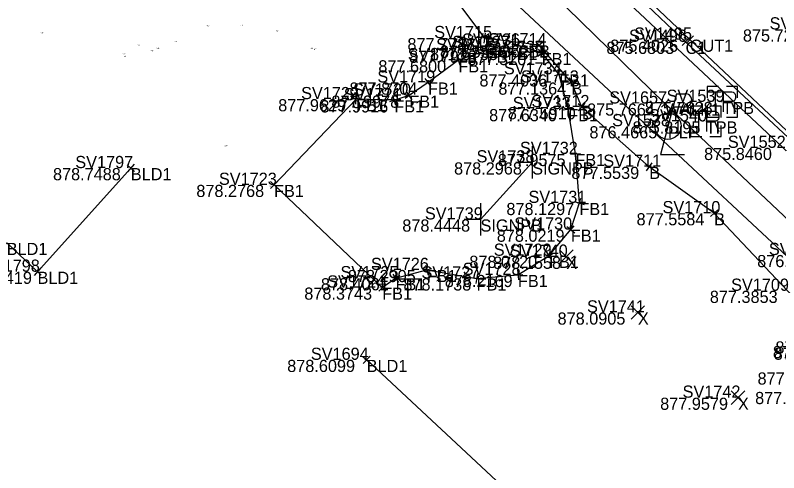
# Model space of a CAD drawing. Extents: x 1469677 to 1493262, y 375219 to 389293.
# Drawn here: x 1480149.3 to 1480224.6, y 379313.5 to 379358.7 of the extents above; entities that cross this region are included whole.
import ezdxf

# ---------------------------------------------------------------- set-up
doc = ezdxf.new("R2010")
doc.units = 0
for name, color, linetype in [('Border', 7, 'Continuous'), ('Default', 7, 'Continuous'), ('DR_X_Drive_Pipe', 7, 'Continuous'), ('DV_X_Lot_Line', 7, 'Continuous'), ('DV_X_Text', 7, 'Continuous'), ('GK_Visualization', 7, 'Continuous'), ('PNTELEV', 7, 'Continuous'), ('PNTS', 7, 'Continuous'), ('RD_P_Text', 7, 'Continuous'), ('RW_P_Esmt_SW', 7, 'Continuous'), ('RW_P_Esmt_U', 7, 'Continuous'), ('rw_x_right_of_way', 7, 'Continuous'), ('SV_P_Mon_Cells_Set', 7, 'Continuous'), ('SV_X_Mon_Cells_Found', 7, 'Continuous'), ('text', 7, 'Continuous'), ('Text Property', 7, 'Continuous')]:
    doc.layers.add(name, color=color, linetype=linetype)

msp = doc.modelspace()

# ---------------------------------------------------------------- linework, layer by layer
at = {"layer": 'Border'}
for points in [[(1480160.694, 379343.603), (1480151.489, 379333.371), (1480148.445, 379336.223), (1480129.012, 379315.639)], [(1480183.972, 379324.669), (1480206.583, 379303.558)]]:
    msp.add_lwpolyline(points, dxfattribs=at)
at = {"layer": 'Default'}
msp.add_lwpolyline([(1480200.308, 379344.167), (1480195.208, 379338.532)], dxfattribs=at)
at = {"layer": 'DR_X_Drive_Pipe'}
msp.add_lwpolyline([(1480327.263, 379249.797), (1480312.798, 379263.799), (1480291.915, 379283.182), (1480274.385, 379298.987), (1480265.401, 379307.725), (1480264.495, 379308.458), (1480240.472, 379331.084), (1480234.677, 379335.863), (1480225.088, 379345.601), (1480208.322, 379361.342), (1480207.346, 379362.25), (1480199.528, 379369.768), (1480193.21, 379375.651), (1480182.823, 379385.139), (1480177.927, 379389.525), (1480169.423, 379398.321), (1480161.035, 379406.189), (1480144.924, 379421.019), (1480134.739, 379430.559), (1480121.485, 379441.998)], dxfattribs=at)
at = {"layer": 'DV_X_Lot_Line'}
msp.add_lwpolyline([(1480327.959, 379242.083), (1480313.163, 379256.356), (1480297.576, 379270.674), (1480283.951, 379284.205), (1480267.344, 379299.69), (1480258.509, 379307.782), (1480244.036, 379321.372), (1480229.243, 379335.021), (1480213.414, 379349.982), (1480196.806, 379366.202), (1480192.296, 379370.271), (1480186.385, 379375.802), (1480181.8, 379379.27), (1480179.258, 379381.212), (1480177.445, 379382.131), (1480174.921, 379382.868), (1480171.98, 379383.537), (1480169.491, 379383.403), (1480167.014, 379382.902), (1480162.891, 379380.83), (1480161.298, 379379.691), (1480158.915, 379377.808)], dxfattribs=at)
at = {"layer": 'PNTELEV'}
for p, q in [((1480195.562, 379355.945), (1480195.694, 379356.936)), ((1480196.124, 379356.375), (1480195.132, 379356.506)), ((1480195.628, 379356.44), (1480195.628, 379356.44)), ((1480198.8, 379355.224), (1480199.104, 379356.177)), ((1480201.321, 379355.352), (1480200.665, 379356.107)), ((1480215.812, 379355.733), (1480215.081, 379356.416)), ((1480215.105, 379355.709), (1480215.788, 379356.44)), ((1480215.447, 379356.074), (1480215.447, 379356.074)), ((1480216.239, 379355.946), (1480215.511, 379356.631)), ((1480215.532, 379355.924), (1480216.218, 379356.653)), ((1480215.875, 379356.288), (1480215.875, 379356.288)), ((1480196.287, 379355.36), (1480195.339, 379355.039)), ((1480195.974, 379354.726), (1480195.652, 379355.673)), ((1480198.375, 379355.576), (1480197.397, 379355.366)), ((1480197.991, 379354.982), (1480197.781, 379355.96)), ((1480197.886, 379355.471), (1480197.886, 379355.471)), ((1480199.428, 379355.549), (1480198.476, 379355.852)), ((1480198.952, 379355.701), (1480198.952, 379355.701)), ((1480200.615, 379355.401), (1480201.371, 379356.057)), ((1480201.562, 379354.585), (1480200.926, 379355.357)), ((1480200.993, 379355.729), (1480200.993, 379355.729)), ((1480193.184, 379353.78), (1480192.862, 379354.727)), ((1480195.813, 379355.199), (1480195.813, 379355.199)), ((1480200.858, 379354.653), (1480201.63, 379355.289)), ((1480201.244, 379354.971), (1480201.244, 379354.971)), ((1480193.497, 379354.414), (1480192.549, 379354.093)), ((1480193.023, 379354.253), (1480193.023, 379354.253)), ((1480203.108, 379352.377), (1480202.858, 379353.345)), ((1480190.43, 379352.353), (1480189.624, 379351.762)), ((1480190.323, 379351.654), (1480189.731, 379352.461)), ((1480202.499, 379352.735), (1480203.467, 379352.986)), ((1480202.983, 379352.861), (1480202.983, 379352.861)), ((1480204.383, 379351.591), (1480203.991, 379352.511)), ((1480190.027, 379352.057), (1480190.027, 379352.057)), ((1480203.727, 379351.855), (1480204.647, 379352.246)), ((1480204.187, 379352.051), (1480204.187, 379352.051)), ((1480182.918, 379349.911), (1480182.948, 379350.911)), ((1480188.589, 379351.054), (1480187.769, 379350.481)), ((1480188.465, 379350.357), (1480187.893, 379351.177)), ((1480183.433, 379350.396), (1480182.433, 379350.426)), ((1480182.933, 379350.411), (1480182.933, 379350.411)), ((1480187.18, 379350.448), (1480186.228, 379350.144)), ((1480186.856, 379349.82), (1480186.552, 379350.772)), ((1480186.704, 379350.296), (1480186.704, 379350.296)), ((1480188.179, 379350.767), (1480188.179, 379350.767)), ((1480213.777, 379349.638), (1480213.051, 379350.325)), ((1480213.071, 379349.618), (1480213.757, 379350.345)), ((1480203.378, 379349.353), (1480204.366, 379349.509)), ((1480203.95, 379348.937), (1480203.794, 379349.925)), ((1480203.872, 379349.431), (1480203.872, 379349.431)), ((1480205.594, 379349.292), (1480204.846, 379349.956)), ((1480204.888, 379349.25), (1480205.552, 379349.998)), ((1480205.22, 379349.624), (1480205.22, 379349.624)), ((1480213.414, 379349.982), (1480213.414, 379349.982)), ((1480204.073, 379344.962), (1480205.069, 379345.044)), ((1480204.612, 379344.505), (1480204.53, 379345.501)), ((1480204.571, 379345.003), (1480204.571, 379345.003)), ((1480212.272, 379343.441), (1480211.458, 379344.023)), ((1480211.574, 379343.326), (1480212.156, 379344.139)), ((1480161.066, 379343.269), (1480160.322, 379343.937)), ((1480161.028, 379343.975), (1480160.36, 379343.231)), ((1480160.694, 379343.603), (1480160.694, 379343.603)), ((1480211.865, 379343.732), (1480211.865, 379343.732)), ((1480175.192, 379341.604), (1480174.47, 379342.295)), ((1480175.177, 379342.311), (1480174.485, 379341.588)), ((1480174.831, 379341.95), (1480174.831, 379341.95)), ((1480204.494, 379340.318), (1480205.446, 379340.013)), ((1480204.817, 379339.689), (1480205.123, 379340.642)), ((1480204.97, 379340.165), (1480204.97, 379340.165)), ((1480217.901, 379338.808), (1480218.627, 379339.495)), ((1480218.608, 379338.789), (1480217.92, 379339.515)), ((1480218.264, 379339.152), (1480218.264, 379339.152)), ((1480203.741, 379337.851), (1480204.509, 379337.21)), ((1480203.804, 379337.147), (1480204.446, 379337.914)), ((1480204.125, 379337.531), (1480204.125, 379337.531)), ((1480201.54, 379334.685), (1480202.392, 379335.21)), ((1480201.703, 379335.373), (1480202.229, 379334.522)), ((1480201.966, 379334.947), (1480201.966, 379334.947)), ((1480151.861, 379333.037), (1480151.117, 379333.706)), ((1480151.823, 379333.743), (1480151.155, 379333)), ((1480189.43, 379333.418), (1480190.396, 379333.673)), ((1480189.785, 379334.029), (1480190.041, 379333.062)), ((1480189.913, 379333.545), (1480189.913, 379333.545)), ((1480198.86, 379333.555), (1480198.944, 379332.559)), ((1480151.489, 379333.371), (1480151.489, 379333.371)), ((1480186.42, 379332.446), (1480187.24, 379333.018)), ((1480186.544, 379333.142), (1480187.116, 379332.322)), ((1480186.83, 379332.732), (1480186.83, 379332.732)), ((1480194.327, 379332.797), (1480195.313, 379332.63)), ((1480194.904, 379333.207), (1480194.736, 379332.221)), ((1480194.82, 379332.714), (1480194.82, 379332.714)), ((1480198.404, 379333.015), (1480199.4, 379333.099)), ((1480198.902, 379333.057), (1480198.902, 379333.057)), ((1480185.144, 379332.154), (1480185.87, 379331.465)), ((1480185.851, 379332.172), (1480185.163, 379331.447)), ((1480185.507, 379331.81), (1480185.507, 379331.81)), ((1480183.607, 379325.01), (1480184.337, 379324.328)), ((1480184.313, 379325.035), (1480183.631, 379324.304)), ((1480183.972, 379324.669), (1480183.972, 379324.669))]:
    msp.add_line(p, q, dxfattribs=at)
at = {"layer": 'PNTS'}
for p, q in [((1480214.563, 379350.941), (1480215.413, 379350.941)), ((1480214.221, 379349.666), (1480215.413, 379349.666))]:
    msp.add_line(p, q, dxfattribs=at)
msp.add_lwpolyline([(1480214.563, 379350.941), (1480212.956, 379344.941), (1480215.356, 379344.941)], dxfattribs=at)
msp.add_circle((1480213.706, 379347.741), 1.3, dxfattribs=at)
msp.add_arc((1480215.425, 379350.303), 0.638, 268.8767, 91.1233, dxfattribs=at)
at = {"layer": 'RD_P_Text'}
for points in [[(1480264.304, 379310.926), (1480249.8, 379324.506), (1480248.109, 379326.126), (1480239.302, 379334.68), (1480237.065, 379336.683), (1480233.83, 379339.39), (1480215.875, 379356.288), (1480200.731, 379370.664), (1480190.903, 379379.712), (1480187.53, 379382.642), (1480185.615, 379384.173), (1480181.928, 379385.583), (1480179.411, 379386.173), (1480174.793, 379387.235), (1480172.715, 379387.432), (1480170.332, 379387.359), (1480168.876, 379387.382), (1480166.808, 379386.944), (1480164.881, 379386.368), (1480162.883, 379385.531), (1480159.898, 379383.853), (1480158.052, 379382.754), (1480156.183, 379381.403), (1480155.05, 379380.342)], [(1480233.297, 379339.4), (1480215.447, 379356.074), (1480200.436, 379370.31), (1480191.889, 379378.223), (1480190.185, 379379.842), (1480188.303, 379381.604), (1480185.259, 379383.605), (1480181.861, 379385.001), (1480179.101, 379385.902), (1480178.705, 379386.045), (1480178.118, 379386.223), (1480177.29, 379386.43), (1480176.688, 379386.511), (1480174.95, 379386.851), (1480173.419, 379387.005), (1480171.202, 379387.128), (1480169.933, 379386.966), (1480168.123, 379386.781), (1480166.87, 379386.446), (1480165.488, 379386.008), (1480163.201, 379385.04), (1480160.165, 379383.332), (1480157.23, 379381.331), (1480156.058, 379380.439)]]:
    msp.add_lwpolyline(points, dxfattribs=at)
at = {"layer": 'RW_P_Esmt_U'}
for p, q in [((1480203.011, 379334.187), (1480204.345, 379335.522)), ((1480203.011, 379335.522), (1480204.345, 379334.187)), ((1480210.073, 379328.679), (1480211.407, 379330.014)), ((1480210.073, 379330.014), (1480211.407, 379328.679)), ((1480219.946, 379320.266), (1480221.28, 379321.601)), ((1480219.946, 379321.601), (1480221.28, 379320.266))]:
    msp.add_line(p, q, dxfattribs=at)
at = {"layer": 'rw_x_right_of_way'}
for p, q in [((1480200.308, 379345.767), (1480200.308, 379342.567)), ((1480200.308, 379344.167), (1480198.708, 379344.167)), ((1480195.208, 379340.132), (1480195.208, 379336.932)), ((1480195.208, 379338.532), (1480193.608, 379338.532))]:
    msp.add_line(p, q, dxfattribs=at)
at = {"layer": 'SV_P_Mon_Cells_Set'}
for p, q in [((1480219.083, 379350.144), (1480219.083, 379350.144)), ((1480217.444, 379348.213), (1480217.444, 379348.213))]:
    msp.add_line(p, q, dxfattribs=at)
for points in [[(1480218.683, 379351.644), (1480217.583, 379351.644), (1480217.583, 379350.544)], [(1480220.582, 379350.544), (1480220.582, 379351.644), (1480219.483, 379351.644)], [(1480217.726, 379351.144), (1480218.97, 379351.144)], [(1480218.356, 379351.144), (1480218.356, 379349.144)], [(1480219.195, 379349.144), (1480219.195, 379351.144), (1480219.95, 379351.144), (1480220.029, 379351.128), (1480220.139, 379351.097), (1480220.186, 379351.065), (1480220.234, 379351.034), (1480220.297, 379350.955), (1480220.344, 379350.876), (1480220.375, 379350.751), (1480220.375, 379350.562), (1480220.36, 379350.499), (1480220.328, 379350.404), (1480220.265, 379350.294), (1480220.202, 379350.247), (1480220.155, 379350.215), (1480220.123, 379350.199), (1480220.076, 379350.184), (1480219.934, 379350.168), (1480219.195, 379350.168)], [(1480219.934, 379350.168), (1480220.375, 379349.144)], [(1480217.044, 379349.713), (1480215.944, 379349.713), (1480215.944, 379348.613)], [(1480217.583, 379349.744), (1480217.583, 379348.644), (1480218.683, 379348.644)], [(1480218.944, 379348.613), (1480218.944, 379349.713), (1480217.844, 379349.713)], [(1480219.483, 379348.644), (1480220.582, 379348.644), (1480220.582, 379349.744)], [(1480216.088, 379349.213), (1480217.332, 379349.213)], [(1480216.718, 379349.213), (1480216.718, 379347.213)], [(1480217.556, 379347.213), (1480217.556, 379349.213), (1480218.312, 379349.213), (1480218.391, 379349.197), (1480218.501, 379349.166), (1480218.548, 379349.134), (1480218.595, 379349.103), (1480218.658, 379349.024), (1480218.706, 379348.945), (1480218.737, 379348.819), (1480218.737, 379348.63), (1480218.721, 379348.567), (1480218.69, 379348.473), (1480218.627, 379348.363), (1480218.564, 379348.316), (1480218.517, 379348.284), (1480218.485, 379348.268), (1480218.438, 379348.253), (1480218.296, 379348.237), (1480217.556, 379348.237)], [(1480215.944, 379347.813), (1480215.944, 379346.713), (1480217.044, 379346.713)], [(1480217.844, 379346.713), (1480218.944, 379346.713), (1480218.944, 379347.813)], [(1480218.296, 379348.237), (1480218.737, 379347.213)]]:
    msp.add_lwpolyline(points, dxfattribs=at)
at = {"layer": 'SV_X_Mon_Cells_Found'}
msp.add_lwpolyline([(1477164.629, 382297.849), (1479615.888, 379904.59), (1480413.414, 379159.216)], dxfattribs=at)
at = {"layer": 'text'}
msp.add_lwpolyline([(1480230.882, 379325.878), (1480225.522, 379331.489), (1480218.264, 379339.152), (1480211.865, 379343.732), (1480205.22, 379349.624), (1480204.187, 379352.051), (1480200.993, 379355.729), (1480195.628, 379356.44), (1480192.91, 379360.091)], dxfattribs=at)
at = {"layer": 'Text Property'}
msp.add_lwpolyline([(1480195.813, 379355.199), (1480193.023, 379354.253), (1480190.027, 379352.057), (1480188.179, 379350.767), (1480186.704, 379350.296), (1480182.933, 379350.411), (1480174.831, 379341.95), (1480185.507, 379331.81), (1480186.83, 379332.732), (1480189.913, 379333.545), (1480194.82, 379332.714), (1480198.902, 379333.057), (1480201.966, 379334.947), (1480204.125, 379337.531), (1480204.97, 379340.165), (1480204.571, 379345.003), (1480203.872, 379349.431), (1480202.983, 379352.861), (1480201.244, 379354.971), (1480198.952, 379355.701), (1480197.886, 379355.471)], close=True, dxfattribs=at)

# ---------------------------------------------------------------- texts
at = {"layer": 'DV_X_Text'}
for s, height, p in [('878.12', 0.06, (1480168.206, 379357.588)), ('878.05', 0.06, (1480171.53, 379357.642)), ('878.17', 0.06, (1480151.826, 379356.898)), ('878.09', 0.06, (1480175.009, 379357.083)), ('875.7225', 1.2, (1480221.105, 379356.097)), ('878.18', 0.06, (1480165.022, 379356.066)), ('877.7788', 1.2, (1480187.994, 379355.24)), ('877.78', 0.06, (1480195.349, 379356.38)), ('875.6803', 1.2, (1480207.633, 379354.874)), ('875.4026', 1.2, (1480208.014, 379355.088)), ('875.68', 0.06, (1480215.165, 379356.014)), ('875.40', 0.06, (1480215.589, 379356.228)), ('878.36', 0.06, (1480161.358, 379355.681)), ('878.34', 0.06, (1480163.27, 379355.378)), ('877.98', 0.06, (1480178.413, 379355.373)), ('878.15', 0.06, (1480178.754, 379355.266)), ('877.5735', 1.2, (1480190.224, 379354.271)), ('877.5546', 1.2, (1480191.205, 379354.501)), ('877.3362', 1.2, (1480193.283, 379354.529)), ('877.57', 0.06, (1480197.607, 379355.411)), ('877.55', 0.06, (1480198.673, 379355.641)), ('877.34', 0.06, (1480200.713, 379355.669)), ('878.29', 0.06, (1480159.878, 379354.801)), ('878.56', 0.06, (1480160.028, 379354.579)), ('878.36', 0.06, (1480162.674, 379355.141)), ('877.7928', 1.2, (1480188.16, 379353.999)), ('877.3201', 1.2, (1480193.919, 379353.771)), ('877.79', 0.06, (1480195.534, 379355.139)), ('877.32', 0.06, (1480200.964, 379354.911)), ('877.6800', 1.2, (1480185.124, 379353.053)), ('877.68', 0.06, (1480192.742, 379354.193)), ('877.4036', 1.2, (1480195.103, 379351.661)), ('877.40', 0.06, (1480202.698, 379352.801)), ('877.8704', 1.2, (1480182.279, 379350.857)), ('877.87', 0.06, (1480189.748, 379351.997)), ('877.1364', 1.2, (1480196.969, 379350.851)), ('877.14', 0.06, (1480203.932, 379351.991)), ('877.9629', 1.2, (1480175.242, 379349.211)), ('877.9916', 1.2, (1480179.401, 379349.096)), ('877.9978', 1.2, (1480180.488, 379349.567)), ('878.18', 0.06, (1480182.385, 379350.552)), ('877.96', 0.06, (1480182.649, 379350.351)), ('877.99', 0.06, (1480186.423, 379350.236)), ('878.00', 0.06, (1480187.888, 379350.707)), ('875.7828', 1.2, (1480211.429, 379348.944)), ('875.78', 0.06, (1480218.803, 379350.084)), ('877.6340', 1.2, (1480196.058, 379348.231)), ('877.5910', 1.2, (1480197.908, 379348.424)), ('877.63', 0.06, (1480203.592, 379349.371)), ('877.59', 0.06, (1480204.94, 379349.564)), ('875.7664', 1.2, (1480205.723, 379348.782)), ('875.77', 0.06, (1480213.135, 379349.922)), ('875.8195', 1.2, (1480210.217, 379347.013)), ('875.82', 0.06, (1480217.164, 379348.153)), ('876.4665', 1.2, (1480205.958, 379346.541)), ('876.47', 0.06, (1480213.424, 379347.681)), ('878.60', 0.06, (1480169.939, 379345.76)), ('875.8460', 1.2, (1480217.274, 379344.401)), ('877.9575', 1.2, (1480196.909, 379343.803)), ('877.96', 0.06, (1480204.287, 379344.943)), ('878.2968', 1.2, (1480192.598, 379342.967)), ('878.30', 0.06, (1480200.022, 379344.107)), ('878.7488', 1.2, (1480153.013, 379342.403)), ('878.75', 0.06, (1480160.415, 379343.543)), ('877.5539', 1.2, (1480204.174, 379342.532)), ('877.55', 0.06, (1480211.586, 379343.672)), ('878.2768', 1.2, (1480167.159, 379340.75)), ('878.57', 0.06, (1480174.361, 379341.757)), ('878.28', 0.06, (1480174.551, 379341.89)), ('878.1297', 1.2, (1480197.762, 379338.965)), ('878.13', 0.06, (1480204.714, 379340.105)), ('877.5584', 1.2, (1480210.611, 379337.952)), ('877.56', 0.06, (1480217.981, 379339.092)), ('878.4448', 1.2, (1480187.489, 379337.332)), ('878.44', 0.06, (1480194.928, 379338.472)), ('878.0219', 1.2, (1480196.813, 379336.331)), ('878.02', 0.06, (1480203.84, 379337.471)), ('876.1212', 1.2, (1480222.517, 379333.821)), ('878.0720', 1.2, (1480194.105, 379333.747)), ('878.1558', 1.2, (1480196.46, 379333.655)), ('878.07', 0.06, (1480201.68, 379334.887)), ('878.16', 0.06, (1480203.418, 379334.795)), ('878.2905', 1.2, (1480182.118, 379332.345)), ('878.29', 0.06, (1480189.633, 379333.485)), ('878.6419', 1.2, (1480144.243, 379332.171)), ('878.64', 0.06, (1480151.208, 379333.311)), ('878.4061', 1.2, (1480179.458, 379331.532)), ('878.41', 0.06, (1480186.572, 379332.672)), ('878.1738', 1.2, (1480187.602, 379331.514)), ('878.2169', 1.2, (1480191.684, 379331.857)), ('878.17', 0.06, (1480194.564, 379332.654)), ('878.22', 0.06, (1480198.623, 379332.997)), ('878.3743', 1.2, (1480177.816, 379330.61)), ('878.37', 0.06, (1480185.226, 379331.75)), ('877.3853', 1.2, (1480217.841, 379330.289)), ('878.0905', 1.2, (1480202.813, 379328.146)), ('878.09', 0.06, (1480210.454, 379329.286)), ('877.4189', 1.2, (1480224.058, 379324.834)), ('877.4361', 1.2, (1480224.313, 379325.293)), ('877.6117', 1.2, (1480224.147, 379324.678)), ('878.6099', 1.2, (1480176.13, 379323.469)), ('878.61', 0.06, (1480183.713, 379324.609)), ('877.6009', 1.2, (1480222.552, 379322.226)), ('877.5908', 1.2, (1480222.312, 379320.303)), ('877.9579', 1.2, (1480212.941, 379319.733)), ('877.96', 0.06, (1480220.329, 379320.873))]:
    msp.add_text(s, height=height, dxfattribs=at).set_placement(p)
at = {"layer": 'GK_Visualization'}
for s, p in [('B', (1480195.628, 379355.24)), ('C1', (1480215.447, 379354.874)), ('GUT1', (1480215.875, 379355.088)), ('FB1', (1480197.886, 379354.271)), ('FB1', (1480198.952, 379354.501)), ('B', (1480200.993, 379354.529)), ('FB1', (1480195.813, 379353.999)), ('FB1', (1480201.244, 379353.771)), ('FB1', (1480193.023, 379353.053)), ('FB1', (1480202.983, 379351.661)), ('FB1', (1480190.027, 379350.857)), ('B', (1480204.187, 379350.851)), ('FB1', (1480182.933, 379349.211)), ('FB1', (1480186.704, 379349.096)), ('FB1', (1480188.179, 379349.567)), ('TPB', (1480219.083, 379348.944)), ('FB1', (1480203.872, 379348.231)), ('B', (1480205.22, 379348.424)), ('WALK1', (1480213.414, 379348.782)), ('TPB', (1480217.444, 379347.013)), ('PLP', (1480213.706, 379346.541)), ('FB1', (1480204.571, 379343.803)), ('SIGNPB', (1480200.308, 379342.967)), ('BLD1', (1480160.694, 379342.403)), ('B', (1480211.865, 379342.532)), ('FB1', (1480174.831, 379340.75)), ('FB1', (1480204.97, 379338.965)), ('B', (1480218.264, 379337.952)), ('SIGNPB', (1480195.208, 379337.332)), ('FB1', (1480204.125, 379336.331)), ('BLD1', (1480148.445, 379335.023)), ('FB1', (1480201.966, 379333.747)), ('X', (1480203.678, 379333.655)), ('FB1', (1480189.913, 379332.345)), ('BLD1', (1480151.489, 379332.171)), ('FB1', (1480186.83, 379331.532)), ('FB1', (1480194.82, 379331.514)), ('FB1', (1480198.902, 379331.857)), ('FB1', (1480185.507, 379330.61)), ('X', (1480210.74, 379328.146)), ('BLD1', (1480183.972, 379323.469)), ('X', (1480220.613, 379319.733))]:
    msp.add_text(s, height=1.2, dxfattribs=at).set_placement(p)
at = {"layer": 'RW_P_Esmt_SW'}
for s, height, p in [('SV1215', 1.2, (1480223.742, 379357.297)), ('SA2050', 0.06, (1480168.154, 379357.648)), ('SA2049', 0.06, (1480171.513, 379357.702)), ('SV1715', 1.2, (1480190.641, 379356.44)), ('SA2083', 0.06, (1480151.78, 379356.958)), ('SA2048', 0.06, (1480174.992, 379357.143)), ('SV1736', 1.2, (1480193.397, 379355.701)), ('SV1714', 1.2, (1480196.015, 379355.729)), ('SV1496', 1.2, (1480209.864, 379356.074)), ('SV1495', 1.2, (1480210.367, 379356.288)), ('SA2051', 0.06, (1480164.999, 379356.126)), ('SV1717', 1.2, (1480190.826, 379355.199)), ('SV1737', 1.2, (1480192.407, 379355.471)), ('SV1715', 0.06, (1480195.379, 379356.44)), ('SV1735', 1.2, (1480195.765, 379354.971)), ('SV1496', 0.06, (1480215.168, 379356.074)), ('SV1495', 0.06, (1480215.6, 379356.288)), ('SA2054', 0.06, (1480161.341, 379355.741)), ('SA2052', 0.06, (1480163.248, 379355.438)), ('SA2047', 0.06, (1480178.391, 379355.433)), ('SA2017', 0.06, (1480178.732, 379355.326)), ('SV1718', 1.2, (1480188.026, 379354.253)), ('SV1737', 0.06, (1480197.612, 379355.471)), ('SV1736', 0.06, (1480198.674, 379355.701)), ('SV1714', 0.06, (1480200.744, 379355.729)), ('SA2055', 0.06, (1480159.855, 379354.861)), ('SA2015', 0.06, (1480160.034, 379354.639)), ('SA2053', 0.06, (1480162.657, 379355.201)), ('SV1717', 0.06, (1480195.564, 379355.199)), ('SV1735', 0.06, (1480200.97, 379354.971)), ('SV1718', 0.06, (1480192.773, 379354.253)), ('SV1734', 1.2, (1480197.513, 379352.861)), ('SV1719', 1.2, (1480185.03, 379352.057)), ('SV1713', 1.2, (1480199.2, 379352.051)), ('SV1734', 0.06, (1480202.71, 379352.861)), ('SV1722', 1.2, (1480177.501, 379350.411)), ('SV1720', 1.2, (1480182.634, 379350.767)), ('SV1719', 0.06, (1480189.777, 379352.057)), ('SV1713', 0.06, (1480203.938, 379352.051)), ('SV1721', 1.2, (1480181.714, 379350.296)), ('SV1720', 0.06, (1480187.902, 379350.767)), ('SV1712', 1.2, (1480200.242, 379349.624)), ('SV1657', 1.2, (1480207.916, 379349.982)), ('SV1539', 1.2, (1480213.575, 379350.144)), ('SA2045', 0.06, (1480182.339, 379350.612)), ('SV1722', 0.06, (1480182.661, 379350.411)), ('SV1721', 0.06, (1480186.454, 379350.296)), ('SV1733', 1.2, (1480198.393, 379349.431)), ('SV1657', 0.06, (1480213.139, 379349.982)), ('SV1539', 0.06, (1480218.808, 379350.144)), ('SV1733', 0.06, (1480203.598, 379349.431)), ('SV1712', 0.06, (1480204.971, 379349.624)), ('SV1540', 1.2, (1480211.851, 379348.213)), ('SV1538', 1.2, (1480208.198, 379347.741)), ('SV1538', 0.06, (1480213.431, 379347.741)), ('SV1540', 0.06, (1480217.164, 379348.213)), ('SV1552', 1.2, (1480219.618, 379345.601)), ('SA2016', 0.06, (1480169.943, 379345.82)), ('SV1732', 1.2, (1480199.101, 379345.003)), ('SV1797', 1.2, (1480155.215, 379343.603)), ('SV1738', 1.2, (1480194.819, 379344.167)), ('SV1732', 0.06, (1480204.298, 379345.003)), ('SV1711', 1.2, (1480207.329, 379343.732)), ('SV1738', 0.06, (1480200.034, 379344.167)), ('SV1797', 0.06, (1480160.42, 379343.603)), ('SV1711', 0.06, (1480211.638, 379343.732)), ('SV1723', 1.2, (1480169.39, 379341.95)), ('SA2046', 0.06, (1480174.335, 379341.817)), ('SV1723', 0.06, (1480174.559, 379341.95)), ('SV1731', 1.2, (1480199.942, 379340.165)), ('SV1710', 1.2, (1480213.173, 379339.152)), ('SV1739', 1.2, (1480189.719, 379338.532)), ('SV1731', 0.06, (1480204.719, 379340.165)), ('SV1730', 1.2, (1480198.542, 379337.531)), ('SV1710', 0.06, (1480218.009, 379339.152)), ('SV1739', 0.06, (1480194.934, 379338.532)), ('SV1730', 0.06, (1480203.846, 379337.531)), ('SV1729', 1.2, (1480196.515, 379334.947)), ('SV1740', 1.2, (1480198.104, 379334.855)), ('SV1656', 1.2, (1480223.669, 379335.021)), ('SV1729', 0.06, (1480201.693, 379334.947)), ('SV1798', 1.2, (1480146, 379333.371)), ('SV1726', 1.2, (1480184.396, 379333.545)), ('SV1728', 1.2, (1480193.451, 379333.057)), ('SV1740', 0.06, (1480203.399, 379334.855)), ('SV1725', 1.2, (1480181.389, 379332.732)), ('SV1727', 1.2, (1480189.379, 379332.714)), ('SV1726', 0.06, (1480189.637, 379333.545)), ('SV1798', 0.06, (1480151.215, 379333.371)), ('SV1724', 1.2, (1480180.075, 379331.81)), ('SV1725', 0.06, (1480186.558, 379332.732)), ('SV1727', 0.06, (1480194.548, 379332.714)), ('SV1728', 0.06, (1480198.629, 379333.057)), ('SV1709', 1.2, (1480219.939, 379331.489)), ('SV1724', 0.06, (1480185.235, 379331.81)), ('SV1741', 1.2, (1480205.721, 379329.346)), ('SV1741', 0.06, (1480210.489, 379329.346)), ('SV1694', 1.2, (1480178.464, 379324.669)), ('SV1694', 0.06, (1480183.697, 379324.669)), ('SV1742', 1.2, (1480215.153, 379320.933)), ('SV1742', 0.06, (1480220.34, 379320.933))]:
    msp.add_text(s, height=height, dxfattribs=at).set_placement(p)

doc.saveas('drawing.dxf')
